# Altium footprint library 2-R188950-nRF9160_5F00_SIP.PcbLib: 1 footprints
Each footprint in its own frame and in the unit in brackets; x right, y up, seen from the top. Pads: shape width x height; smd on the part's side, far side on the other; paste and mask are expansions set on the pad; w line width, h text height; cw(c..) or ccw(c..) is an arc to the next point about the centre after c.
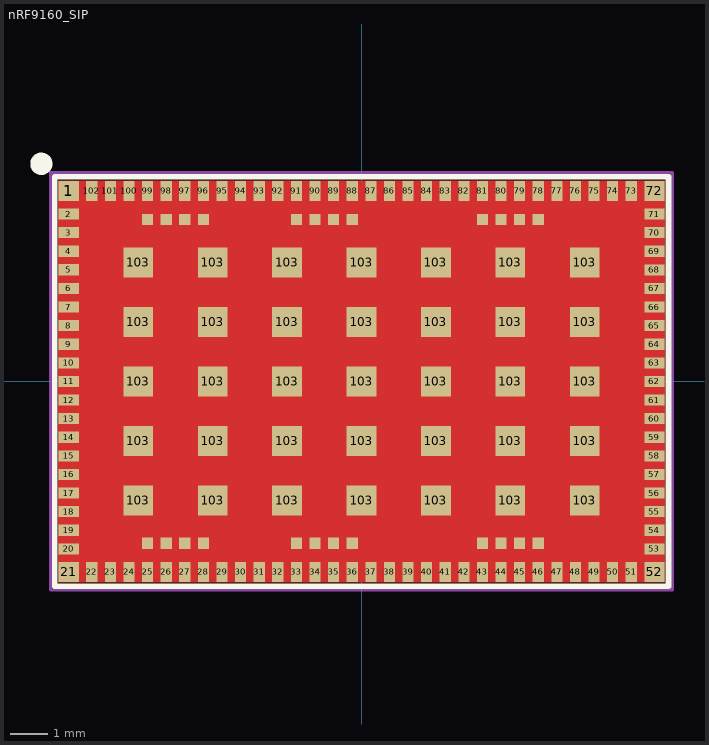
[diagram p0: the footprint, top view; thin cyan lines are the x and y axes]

## nRF9160_SIP [mm]
height 1
pads (161):
  rect 0.54x0.54 smd mask+0.05: 1(-7.87,5.12) 21(-7.87,-5.12) 52(7.87,-5.12) 72(7.87,5.12)
  rect 0.54x0.3 smd mask+0.05: 2(-7.87,4.5) 3(-7.87,4) 4(-7.87,3.5) 5(-7.87,3) 6(-7.87,2.5) 7(-7.87,2) 8(-7.87,1.5) 9(-7.87,1) 10(-7.87,0.5) 11(-7.87,0) 12(-7.87,-0.5) 13(-7.87,-1) 14(-7.87,-1.5) 15(-7.87,-2) 16(-7.87,-2.5) 17(-7.87,-3) 18(-7.87,-3.5) 19(-7.87,-4) 20(-7.87,-4.5) 53(7.87,-4.5) 54(7.87,-4) 55(7.87,-3.5) 56(7.87,-3) 57(7.87,-2.5) 58(7.87,-2) 59(7.87,-1.5) 60(7.87,-1) 61(7.87,-0.5) 62(7.87,0) 63(7.87,0.5) 64(7.87,1) 65(7.87,1.5) 66(7.87,2) 67(7.87,2.5) 68(7.87,3) 69(7.87,3.5) 70(7.87,4) 71(7.87,4.5)
  rect 0.3x0.54 smd mask+0.05: 22(-7.25,-5.12) 23(-6.75,-5.12) 24(-6.25,-5.12) 25(-5.75,-5.12) 26(-5.25,-5.12) 27(-4.75,-5.12) 28(-4.25,-5.12) 29(-3.75,-5.12) 30(-3.25,-5.12) 31(-2.75,-5.12) 32(-2.25,-5.12) 33(-1.75,-5.12) 34(-1.25,-5.12) 35(-0.75,-5.12) 36(-0.25,-5.12) 37(0.25,-5.12) 38(0.75,-5.12) 39(1.25,-5.12) 40(1.75,-5.12) 41(2.25,-5.12) 42(2.75,-5.12) 43(3.25,-5.12) 44(3.75,-5.12) 45(4.25,-5.12) 46(4.75,-5.12) 47(5.25,-5.12) 48(5.75,-5.12) 49(6.25,-5.12) 50(6.75,-5.12) 51(7.25,-5.12) 73(7.25,5.12) 74(6.75,5.12) 75(6.25,5.12) 76(5.75,5.12) 77(5.25,5.12) 78(4.75,5.12) 79(4.25,5.12) 80(3.75,5.12) 81(3.25,5.12) 82(2.75,5.12) 83(2.25,5.12) 84(1.75,5.12) 85(1.25,5.12) 86(0.75,5.12) 87(0.25,5.12) 88(-0.25,5.12) 89(-0.75,5.12) 90(-1.25,5.12) 91(-1.75,5.12) 92(-2.25,5.12) 93(-2.75,5.12) 94(-3.25,5.12) 95(-3.75,5.12) 96(-4.25,5.12) 97(-4.75,5.12) 98(-5.25,5.12) 99(-5.75,5.12) 100(-6.25,5.12) 101(-6.75,5.12) 102(-7.25,5.12)
  rect 0.8x0.8 smd mask+0.05: 103(-6,-3.2) 103(-6,-1.6) 103(-6,0) 103(-6,1.6) 103(-6,3.2) 103(-4,-3.2) 103(-4,-1.6) 103(-4,0) 103(-4,1.6) 103(-4,3.2) 103(-2,-3.2) 103(-2,-1.6) 103(-2,0) 103(-2,1.6) 103(-2,3.2) 103(0,-3.2) 103(0,-1.6) 103(0,0) 103(0,1.6) 103(0,3.2) 103(2,-3.2) 103(2,-1.6) 103(2,0) 103(2,1.6) 103(2,3.2) 103(4,-3.2) 103(4,-1.6) 103(4,0) 103(4,1.6) 103(4,3.2) 103(6,-3.2) 103(6,-1.6) 103(6,0) 103(6,1.6) 103(6,3.2)
  rect 0.3x0.3 smd mask+0.05: 104(-5.75,-4.35) 105(-5.25,-4.35) 106(-4.75,-4.35) 107(-4.25,-4.35) 108(-1.75,-4.35) 109(-1.25,-4.35) 110(-0.75,-4.35) 111(-0.25,-4.35) 112(3.25,-4.35) 113(3.75,-4.35) 114(4.25,-4.35) 115(4.75,-4.35) 116(4.75,4.35) 117(4.25,4.35) 118(3.75,4.35) 119(3.25,4.35) 120(-0.25,4.35) 121(-0.75,4.35) 122(-1.25,4.35) 123(-1.75,4.35) 124(-4.25,4.35) 125(-4.75,4.35) 126(-5.25,4.35) 127(-5.75,4.35)
Top Layer:
  pour cut-out: -8.15,5.4 8.15,5.4 8.15,-5.4 -8.15,-5.4
Top Overlay:
  circle w0.3: c-8.605,5.85 r0.15
  lines w0.15: -8.25,-5.5 8.25,-5.5 8.25,5.5 -8.25,5.5 -8.25,-5.5
Mechanical 7:
  circle w0.3: c-6.5,3.75 r0.15
  lines w0.1: -8.05,-5.3 8.05,-5.3 8.05,5.3 -8.05,5.3 -8.05,-5.3
Mechanical 15:
  circle w0.3: c-6.5,3.75 r0.15
  lines w0.1: -8.35,-5.6 -8.35,5.6 8.35,5.6 8.35,-5.6 -8.35,-5.6
3D body "nRF9160_v5.step": height 1.2, standoff 0, extent -8.05,-5.3 8.05,5.3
